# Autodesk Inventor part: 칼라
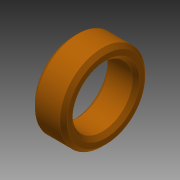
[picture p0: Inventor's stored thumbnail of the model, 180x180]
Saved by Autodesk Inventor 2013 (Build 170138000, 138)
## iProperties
Created: 2016-10
Part Number: 칼라
Material: 강철, 연강
Document SubType Name: Modeling
Designer: mduedu
Density: 1 g/cm^3
Author: mduedu
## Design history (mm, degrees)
sketch "스케치1"
  geometry: C1 r 12 at (0, 0); C2 r 8.5 at (0, 0); 1 further point
  constraints: 2 centre point, 2 coincident
  dimensions: "d0" = 24 diameter of C1; "d1" = 17 diameter of C2
extrude "돌출1" new body sketch "스케치1" distance "d2" = 9; taper "d3" = 0 deg
chamfer "모따기1" distance "d4" = 1; stored, may be unused: second distance "d5" = 2, angle "d6" = 45 deg
node "솔리드1"
